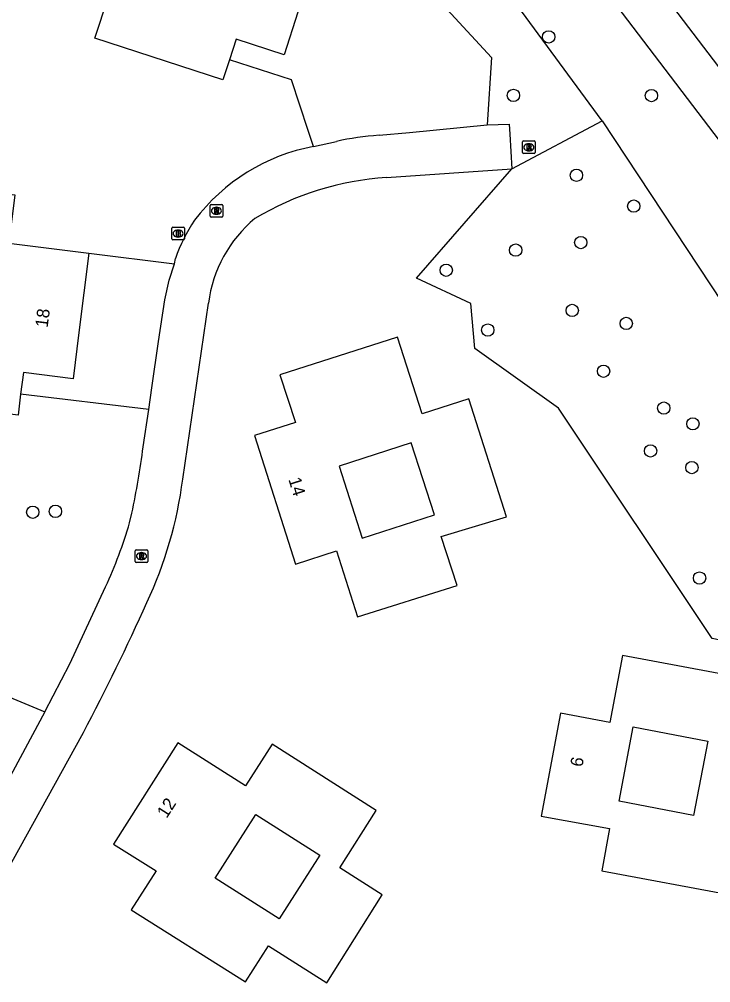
# Model space of a CAD drawing. Extents: x 156664 to 157568, y 383571 to 384421.
# Drawn here: x 156849.9 to 156904.8, y 384131.5 to 384208.1 of the extents above; entities that cross this region are included whole.
import ezdxf

# ---------------------------------------------------------------- set-up
doc = ezdxf.new("R2010")
doc.units = 0
for name, color, linetype in [('IMGEO_Boom', 7, 'Continuous'), ('IMGEO_Brandkraan', 7, 'Continuous'), ('IMGEO_Fietspad_gesloten', 7, 'Continuous'), ('IMGEO_Groenvoorziening', 7, 'Continuous'), ('IMGEO_Loofbos', 7, 'Continuous'), ('IMGEO_Pand', 7, 'Continuous'), ('IMGEO_Pand_nummerreeks', 7, 'Continuous'), ('IMGEO_Rijbaan_lokaal_gesloten', 7, 'Continuous'), ('IMGEO_Rioolput', 7, 'Continuous')]:
    doc.layers.add(name, color=color, linetype=linetype)

msp = doc.modelspace()

# ---------------------------------------------------------------- linework, layer by layer
at = {"layer": 'IMGEO_Boom'}
for centre in [(156891.939, 384206.689), (156889.136, 384202.044), (156900.103, 384202.022), (156894.148, 384195.688), (156898.69, 384193.242), (156894.485, 384190.346), (156889.319, 384189.747), (156883.802, 384188.145), (156893.807, 384184.951), (156887.103, 384183.396), (156898.103, 384183.916), (156896.299, 384180.124), (156901.082, 384177.196), (156903.39, 384175.94), (156900.031, 384173.783), (156903.311, 384172.461), (156850.973, 384168.919), (156852.772, 384168.987), (156903.918, 384163.688)]:
    msp.add_circle(centre, 0.489, dxfattribs=at)
at = {"layer": 'IMGEO_Brandkraan'}
for p, q in [((156862.015, 384190.633), (156862.015, 384191.485)), ((156862.09, 384191.559), (156862.942, 384191.559)), ((156863.016, 384191.485), (156863.016, 384190.633)), ((156862.526, 384190.779), (156862.501, 384190.779)), ((156862.503, 384191.339), (156862.528, 384191.339)), ((156862.942, 384190.559), (156862.09, 384190.559))]:
    msp.add_line(p, q, dxfattribs=at)
for points in [[(156862.015, 384190.633), (156862.015, 384191.485)], [(156862.09, 384191.559), (156862.942, 384191.559)], [(156863.016, 384191.485), (156863.016, 384190.633)], [(156862.363, 384191.259), (156862.363, 384190.859), (156862.576, 384190.859)], [(156862.594, 384191.259), (156862.363, 384191.259)], [(156862.542, 384191.178), (156862.488, 384191.178), (156862.488, 384191.102)], [(156862.488, 384191.102), (156862.541, 384191.102)], [(156862.55, 384191.026), (156862.488, 384191.026), (156862.488, 384190.945)], [(156862.488, 384190.945), (156862.55, 384190.945)], [(156862.942, 384190.559), (156862.09, 384190.559)]]:
    msp.add_lwpolyline(points, dxfattribs=at)
for centre, radius, start, end in [((156862.092, 384191.483), 0.0765, 91.55205, 178.44795), ((156862.092, 384191.483), 0.0765, 91.55205, 178.44795), ((156862.94, 384191.483), 0.0765, 1.55205, 88.44795), ((156862.94, 384191.483), 0.0765, 1.55205, 88.44795), ((156862.092, 384190.635), 0.0765, 181.55205, 268.44795), ((156862.092, 384190.635), 0.0765, 181.55205, 268.44795), ((156862.543, 384191.14), 0.0379, 267.82845, 90.93552), ((156862.551, 384190.985), 0.0404, 269.87594, 90.50774), ((156862.582, 384191.11), 0.251, 268.66757, 293.53466), ((156862.598, 384191.114), 0.145, 59.4692, 91.53667), ((156862.623, 384191.161), 0.0922, 285.51372, 58.15012), ((156862.628, 384190.969), 0.105, 301.31148, 78.98903), ((156862.94, 384190.635), 0.0765, 271.55205, 358.44795), ((156862.94, 384190.635), 0.0765, 271.55205, 358.44795)]:
    msp.add_arc(centre, radius, start, end, dxfattribs=at)
for centre, major_axis, ratio, start_param, end_param in [((156862.502, 384191.059), (-0.387, 0.002), 0.722429, 4.712389, 7.853982), ((156862.527, 384191.059), (-0.39, 0.002), 0.717154, 1.570796, 4.712389)]:
    msp.add_ellipse(centre, major_axis=major_axis, ratio=ratio, start_param=start_param, end_param=end_param, dxfattribs=at)
at = {"layer": 'IMGEO_Fietspad_gesloten'}
for points in [[(156849.254, 384272.327), (156925.032, 384172.754), (156949.045, 384141.371)], [(156945.927, 384151.336), (156927.81, 384174.952), (156867.867, 384253.653)]]:
    msp.add_lwpolyline(points, dxfattribs=at)
at = {"layer": 'IMGEO_Groenvoorziening'}
for points in [[(156896.18, 384200.013), (156851.427, 384260.941)], [(156873.961, 384214.559), (156880.686, 384212.359), (156887.401, 384205.04), (156887.053, 384199.698)], [(156873.276, 384197.981), (156872.855, 384199.253), (156871.527, 384203.266), (156866.597, 384204.873)], [(156855.43, 384189.495), (156862.225, 384188.659)], [(156860.187, 384177.083), (156850.013, 384178.291)], [(156844.783, 384156.013), (156851.936, 384153.054)]]:
    msp.add_lwpolyline(points, dxfattribs=at)
at = {"layer": 'IMGEO_Loofbos'}
for points in [[(156889.009, 384196.195), (156896.18, 384200.013)], [(156896.18, 384200.013), (156920.073, 384163.8), (156911.353, 384157.536)], [(156911.353, 384157.536), (156904.931, 384158.876), (156892.709, 384177.194), (156886.083, 384181.928), (156885.768, 384185.506), (156881.456, 384187.505), (156889.009, 384196.195)]]:
    msp.add_lwpolyline(points, dxfattribs=at)
at = {"layer": 'IMGEO_Pand'}
for points in [[(156866.597, 384204.873), (156866.069, 384203.268), (156855.917, 384206.59), (156856.974, 384209.822), (156851.734, 384211.527), (156854.296, 384219.378), (156858.108, 384218.134), (156859.786, 384223.277), (156869.084, 384220.243), (156867.877, 384216.545), (156873.961, 384214.559)], [(156873.961, 384214.559), (156872.032, 384208.65), (156870.925, 384205.255), (156867.13, 384206.495), (156866.597, 384204.873)], [(156850.013, 384178.291), (156849.805, 384176.629), (156839.204, 384177.937), (156839.62, 384181.311), (156834.165, 384181.975), (156835.167, 384190.214), (156839.154, 384189.729), (156839.855, 384195.355), (156849.56, 384194.146), (156849.079, 384190.286), (156855.43, 384189.495)], [(156855.43, 384189.495), (156854.647, 384183.209), (156854.186, 384179.514), (156850.228, 384180.007), (156850.013, 384178.291)], [(156885.611, 384177.916), (156881.895, 384176.737), (156879.937, 384182.83), (156870.583, 384179.841), (156871.827, 384176.044), (156868.572, 384175.009), (156871.829, 384164.801), (156875.084, 384165.84), (156876.751, 384160.602), (156884.673, 384163.097), (156883.415, 384166.995), (156888.599, 384168.555), (156885.611, 384177.916)], [(156882.865, 384168.698), (156881.016, 384174.427), (156875.293, 384172.58), (156877.142, 384166.851), (156882.865, 384168.698)], [(156913.042, 384150.679), (156906.712, 384151.876), (156907.432, 384155.736), (156897.796, 384157.534), (156896.804, 384152.211), (156892.871, 384152.959), (156891.354, 384144.753), (156896.776, 384143.771), (156896.154, 384140.409), (156906.669, 384138.463), (156907.289, 384141.798), (156911.225, 384141.066), (156913.042, 384150.679)], [(156898.652, 384151.859), (156904.567, 384150.734), (156903.443, 384144.827), (156897.528, 384145.952), (156898.652, 384151.859)], [(156878.247, 384145.221), (156869.985, 384150.476), (156867.874, 384147.177), (156862.49, 384150.597), (156857.394, 384142.547), (156860.766, 384140.413), (156858.8, 384137.317), (156867.875, 384131.591), (156869.687, 384134.452), (156874.338, 384131.527), (156878.732, 384138.517), (156875.351, 384140.668), (156878.247, 384145.221)], [(156870.54, 384136.603), (156865.461, 384139.833), (156868.688, 384144.906), (156873.766, 384141.676), (156870.54, 384136.603)]]:
    msp.add_lwpolyline(points, dxfattribs=at)
at = {"layer": 'IMGEO_Rijbaan_lokaal_gesloten'}
for points in [[(156878.469, 384198.871), (156880.897, 384199.085), (156887.053, 384199.698)], [(156887.053, 384199.698), (156888.801, 384199.741), (156888.846, 384198.97), (156889.009, 384196.195)], [(156873.276, 384197.981), (156875.087, 384198.385)], [(156879.074, 384195.504), (156889.009, 384196.195)], [(156862.225, 384188.659), (156862.308, 384189.069)], [(156860.187, 384177.083), (156860.435, 384178.797), (156860.969, 384182.483), (156861.466, 384185.786), (156861.796, 384187.367), (156862.225, 384188.659)], [(156862.886, 384171.545), (156864.923, 384185.542)], [(156859.745, 384174.109), (156860.187, 384177.083)], [(156858.67, 384168.076), (156858.839, 384168.84)], [(156851.936, 384153.054), (156853.914, 384156.859), (156856.76, 384162.991)], [(156851.936, 384153.054), (156848.989, 384147.571), (156847.291, 384144.543), (156846.369, 384142.937)], [(156845.957, 384135.061), (156854.995, 384151.422)]]:
    msp.add_lwpolyline(points, dxfattribs=at)
for centre, radius, start, end in [((156880.252, 384174.455), 24.481, 94.17602, 102.17905), ((156876.099, 384182.888), 15.355, 100.59367, 143.05005), ((156880.467, 384172.559), 22.987, 93.47345, 121.04804), ((156875.318, 384184.198), 10.481, 129.78358, 172.63482), ((156874.161, 384185.063), 12.512, 145.67788, 161.3274), ((156797.327, 384182.129), 62.932, 347.80895, 352.67795), ((156830.416, 384175.686), 32.733, 334.78913, 352.73266), ((156824.03, 384178.186), 36.085, 335.09667, 343.72952), ((156700.922, 384232.989), 174.332, 332.10301, 335.87805)]:
    msp.add_arc(centre, radius, start, end, dxfattribs=at)
at = {"layer": 'IMGEO_Rioolput'}
for p, q in [((156889.867, 384197.491), (156889.867, 384198.343)), ((156889.942, 384198.417), (156890.794, 384198.417)), ((156890.868, 384198.343), (156890.868, 384197.491)), ((156890.378, 384197.637), (156890.353, 384197.637)), ((156890.355, 384198.197), (156890.38, 384198.197)), ((156890.794, 384197.417), (156889.942, 384197.417)), ((156865.059, 384192.443), (156865.059, 384193.295)), ((156865.134, 384193.369), (156865.986, 384193.369)), ((156865.547, 384193.149), (156865.572, 384193.149)), ((156866.06, 384193.295), (156866.06, 384192.443)), ((156865.986, 384192.369), (156865.134, 384192.369)), ((156865.57, 384192.589), (156865.545, 384192.589)), ((156859.107, 384165.002), (156859.107, 384165.854)), ((156859.182, 384165.928), (156860.034, 384165.928)), ((156859.595, 384165.708), (156859.62, 384165.708)), ((156860.108, 384165.854), (156860.108, 384165.002)), ((156860.034, 384164.928), (156859.182, 384164.928)), ((156859.618, 384165.148), (156859.593, 384165.148))]:
    msp.add_line(p, q, dxfattribs=at)
for points in [[(156889.867, 384197.491), (156889.867, 384198.343)], [(156889.942, 384198.417), (156890.794, 384198.417)], [(156890.868, 384198.343), (156890.868, 384197.491)], [(156890.456, 384198.115), (156890.204, 384198.117), (156890.204, 384197.717)], [(156890.204, 384197.717), (156890.328, 384197.717), (156890.328, 384197.879), (156890.339, 384197.879)], [(156890.382, 384198.036), (156890.328, 384198.036), (156890.328, 384197.955)], [(156890.328, 384197.955), (156890.38, 384197.955)], [(156890.386, 384197.85), (156890.457, 384197.717), (156890.597, 384197.717), (156890.532, 384197.843)], [(156890.794, 384197.417), (156889.942, 384197.417)], [(156865.059, 384192.443), (156865.059, 384193.295)], [(156865.134, 384193.369), (156865.986, 384193.369)], [(156865.648, 384193.067), (156865.396, 384193.069), (156865.396, 384192.669)], [(156865.574, 384192.988), (156865.52, 384192.988), (156865.52, 384192.907)], [(156865.52, 384192.907), (156865.572, 384192.907)], [(156866.06, 384193.295), (156866.06, 384192.443)], [(156865.986, 384192.369), (156865.134, 384192.369)], [(156865.396, 384192.669), (156865.52, 384192.669), (156865.52, 384192.831), (156865.531, 384192.831)], [(156865.578, 384192.802), (156865.649, 384192.669), (156865.789, 384192.669), (156865.724, 384192.795)], [(156859.107, 384165.002), (156859.107, 384165.854)], [(156859.182, 384165.928), (156860.034, 384165.928)], [(156859.696, 384165.626), (156859.444, 384165.628), (156859.444, 384165.228)], [(156859.444, 384165.228), (156859.568, 384165.228), (156859.568, 384165.39), (156859.579, 384165.39)], [(156859.622, 384165.547), (156859.568, 384165.547), (156859.568, 384165.466)], [(156859.568, 384165.466), (156859.62, 384165.466)], [(156859.626, 384165.361), (156859.697, 384165.228), (156859.837, 384165.228), (156859.772, 384165.354)], [(156860.108, 384165.854), (156860.108, 384165.002)], [(156860.034, 384164.928), (156859.182, 384164.928)]]:
    msp.add_lwpolyline(points, dxfattribs=at)
for centre, radius, start, end in [((156889.944, 384198.341), 0.0765, 91.55205, 178.44795), ((156889.944, 384198.341), 0.0765, 91.55205, 178.44795), ((156890.792, 384198.341), 0.0765, 1.55205, 88.44795), ((156890.792, 384198.341), 0.0765, 1.55205, 88.44795), ((156889.944, 384197.493), 0.0765, 181.55205, 268.44795), ((156889.944, 384197.493), 0.0765, 181.55205, 268.44795), ((156890.338, 384197.826), 0.0533, 26.02933, 88.69889), ((156890.364, 384198.144), 0.19, 274.7715, 282.96867), ((156890.388, 384197.94), 0.0964, 77.00612, 93.18647), ((156890.402, 384197.997), 0.0378, 276.66336, 79.67722), ((156890.455, 384198.005), 0.109, 350.36119, 89.41601), ((156890.453, 384198.005), 0.112, 277.58423, 350.98172), ((156890.437, 384197.79), 0.108, 29.51342, 73.79051), ((156890.792, 384197.493), 0.0765, 271.55205, 358.44795), ((156890.792, 384197.493), 0.0765, 271.55205, 358.44795), ((156865.136, 384193.293), 0.0765, 91.55205, 178.44795), ((156865.136, 384193.293), 0.0765, 91.55205, 178.44795), ((156865.556, 384193.096), 0.19, 274.7715, 282.96867), ((156865.58, 384192.892), 0.0964, 77.00612, 93.18647), ((156865.594, 384192.949), 0.0378, 276.66336, 79.67722), ((156865.647, 384192.957), 0.109, 350.36119, 89.41601), ((156865.645, 384192.957), 0.112, 277.58423, 350.98172), ((156865.984, 384193.293), 0.0765, 1.55205, 88.44795), ((156865.984, 384193.293), 0.0765, 1.55205, 88.44795), ((156865.136, 384192.445), 0.0765, 181.55205, 268.44795), ((156865.136, 384192.445), 0.0765, 181.55205, 268.44795), ((156865.53, 384192.778), 0.0533, 26.02933, 88.69889), ((156865.629, 384192.742), 0.108, 29.51342, 73.79051), ((156865.984, 384192.445), 0.0765, 271.55205, 358.44795), ((156865.984, 384192.445), 0.0765, 271.55205, 358.44795), ((156859.184, 384165.852), 0.0765, 91.55205, 178.44795), ((156859.184, 384165.852), 0.0765, 91.55205, 178.44795), ((156859.578, 384165.337), 0.0533, 26.02933, 88.69889), ((156859.604, 384165.655), 0.19, 274.7715, 282.96867), ((156859.628, 384165.451), 0.0964, 77.00612, 93.18647), ((156859.642, 384165.508), 0.0378, 276.66336, 79.67722), ((156859.695, 384165.516), 0.109, 350.36119, 89.41601), ((156859.693, 384165.516), 0.112, 277.58423, 350.98172), ((156859.677, 384165.301), 0.108, 29.51342, 73.79051), ((156860.032, 384165.852), 0.0765, 1.55205, 88.44795), ((156860.032, 384165.852), 0.0765, 1.55205, 88.44795), ((156859.184, 384165.004), 0.0765, 181.55205, 268.44795), ((156859.184, 384165.004), 0.0765, 181.55205, 268.44795), ((156860.032, 384165.004), 0.0765, 271.55205, 358.44795), ((156860.032, 384165.004), 0.0765, 271.55205, 358.44795)]:
    msp.add_arc(centre, radius, start, end, dxfattribs=at)
for centre, major_axis, ratio, start_param, end_param in [((156890.354, 384197.917), (-0.387, 0.002), 0.722429, 4.712389, 7.853982), ((156890.379, 384197.917), (-0.39, 0.002), 0.717154, 1.570796, 4.712389), ((156865.546, 384192.869), (-0.387, 0.002), 0.722429, 4.712389, 7.853982), ((156865.571, 384192.869), (-0.39, 0.002), 0.717154, 1.570796, 4.712389), ((156859.594, 384165.428), (-0.387, 0.002), 0.722429, 4.712389, 7.853982), ((156859.619, 384165.428), (-0.39, 0.002), 0.717154, 1.570796, 4.712389)]:
    msp.add_ellipse(centre, major_axis=major_axis, ratio=ratio, start_param=start_param, end_param=end_param, dxfattribs=at)

# ---------------------------------------------------------------- texts
at = {"layer": 'IMGEO_Pand_nummerreeks'}
for s, rotation, p in [('18', 82.93543, (156852.157, 384183.556)), ('14', 287.49792, (156871.262, 384171.523)), ('6', 79.32601, (156894.612, 384148.629)), ('12', 57.46767, (156861.61, 384144.539))]:
    msp.add_text(s, height=1, rotation=rotation, dxfattribs=at).set_placement(p)

doc.saveas('drawing.dxf')
